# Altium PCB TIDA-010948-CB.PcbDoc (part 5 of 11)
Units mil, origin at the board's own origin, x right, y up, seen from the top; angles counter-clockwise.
Board outline 8100 x 8400 mil, 8 copper layers (L01 - TOP, L02 - GND, L03 - SIG, L04 - GND, L05 - PWR, L06 - SIG, L07 - GND, L08 - BOTTOM), stack 59.656 mil thick; 711 components, 572 nets, 2646 pads, 1325 vias.
Unrouted connection lines stored in the file: 988.
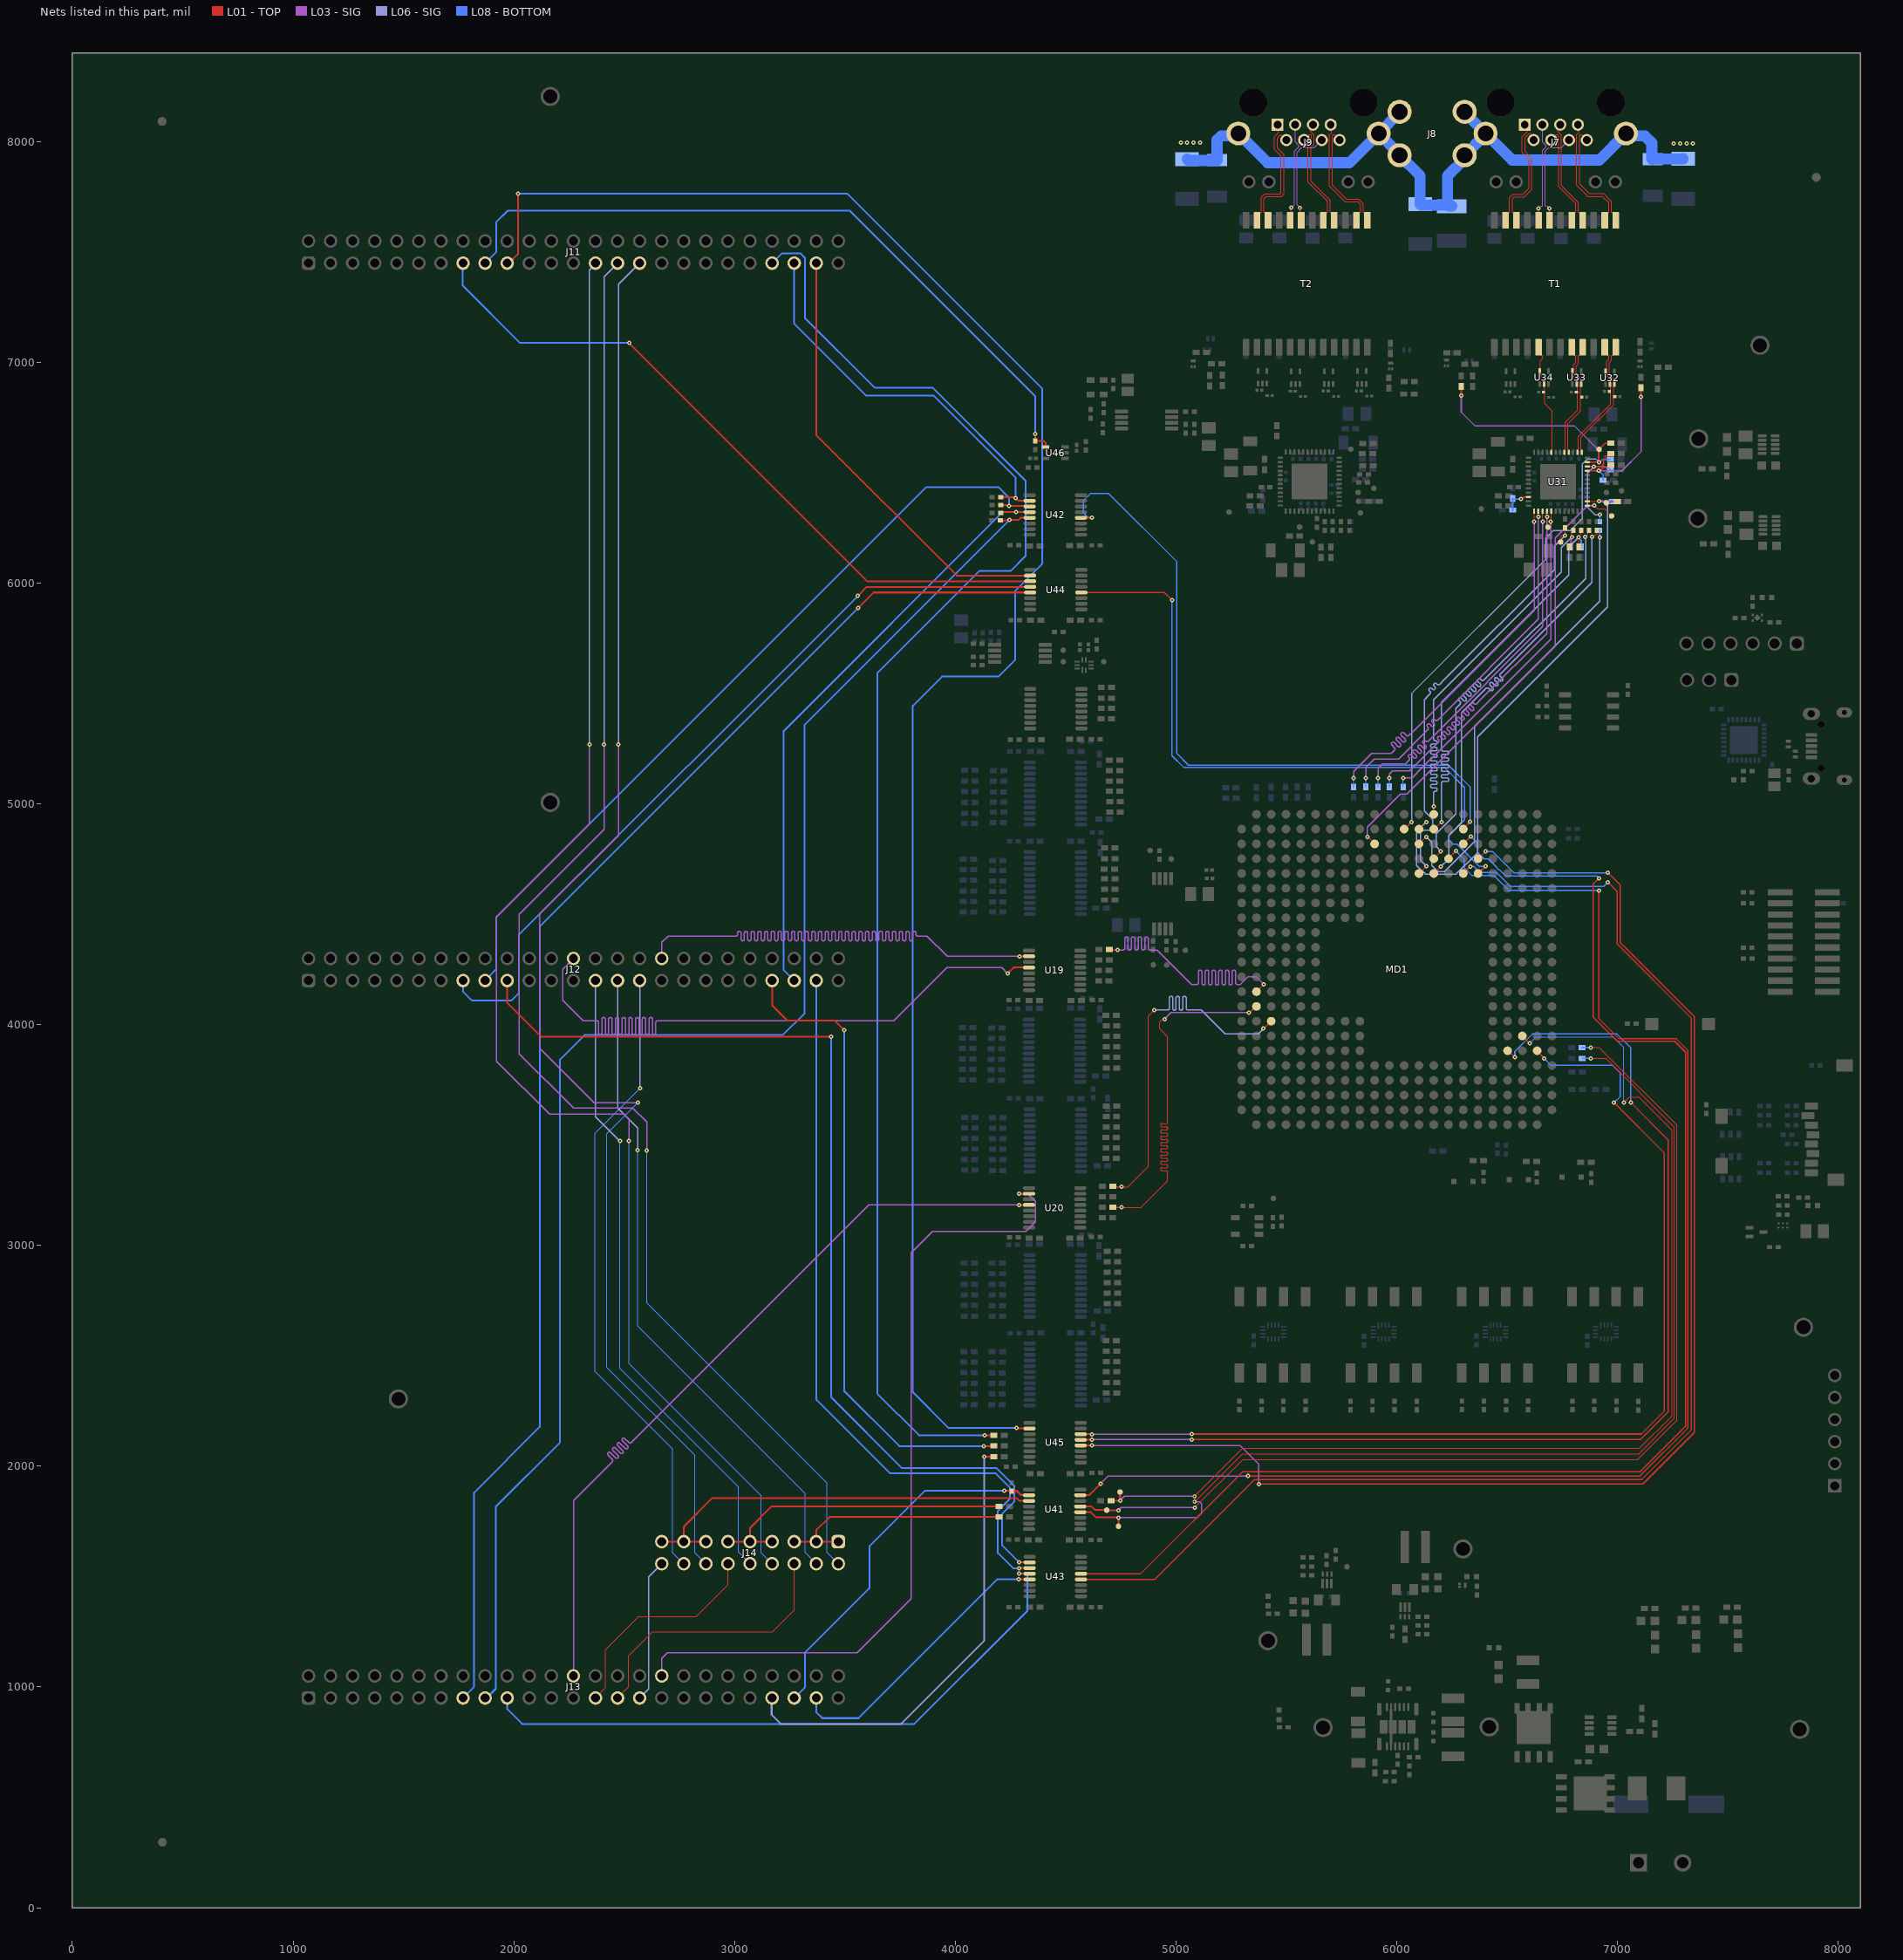
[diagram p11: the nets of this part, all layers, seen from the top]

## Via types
v1: diameter 19.68, hole 7.87, L01 - TOP to L08 - BOTTOM, 1310 vias
v2: diameter 20, hole 7.87, L01 - TOP to L08 - BOTTOM, tented both sides, 7 vias
v3: diameter 200, hole 144, L01 - TOP to L08 - BOTTOM, 6 vias
v4: diameter 20, hole 8, L01 - TOP to L08 - BOTTOM, tented both sides, 2 vias

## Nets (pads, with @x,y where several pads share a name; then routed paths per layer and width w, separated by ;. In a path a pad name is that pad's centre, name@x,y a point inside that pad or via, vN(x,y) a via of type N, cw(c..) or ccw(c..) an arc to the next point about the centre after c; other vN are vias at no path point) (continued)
DOUT_B3_SDM: J12.26 U19.12 | length 3736.3
  L01 - TOP w8: v1(4237,4231.5) 4264.07,4258.57 U19.12@4336.5,4258.57
  L03 - SIG w5.25: J12.26@2270,4299.6 2221.5,4251.1 2221.5,4110.5 2314.5,4017.5 2344.81,4017.5 2376.13,4017.5 cw(c2376.13,4009.88) 2383.75,4009.88 2383.75,3962.17 ccw(c2391.38,3962.17) 2399,3962.17 2399,4024.62 cw(c2406.63,4024.62) 2414.25,4024.62 2414.25,3962.17 ccw(c2421.88,3962.17) 2429.5,3962.17 2429.5,4024.62 cw(c2437.13,4024.62) 2444.75,4024.62 2444.75,3962.17 ccw(c2452.38,3962.17) 2460,3962.17 2460,4024.62 cw(c2467.63,4024.62) 2475.25,4024.62 2475.25,3962.17 ccw(c2482.88,3962.17) 2490.5,3962.17 2490.5,4024.62 cw(c2498.13,4024.62) 2505.75,4024.62 2505.75,3962.17 ccw(c2513.38,3962.17) 2521,3962.17 2521,4024.62 cw(c2528.63,4024.62) 2536.25,4024.62 2536.25,3962.17 ccw(c2543.88,3962.17) 2551.5,3962.17 2551.5,4024.62 cw(c2559.13,4024.62) 2566.75,4024.62 2566.75,3962.17 ccw(c2574.38,3962.17) 2582,3962.17 2582,4024.62 cw(c2589.63,4024.62) 2597.25,4024.62 2597.25,3962.17 ccw(c2604.88,3962.17) 2612.5,3962.17 2612.5,4024.62 cw(c2620.13,4024.62) 2627.75,4024.62 2627.75,3962.17 ccw(c2635.38,3962.17) 2643,3962.17 2643,4009.88 cw(c2650.63,4009.88) 2650.63,4017.5 2653.25,4017.5 3721.5,4017.5 3962.51,4258.51 4209.99,4258.51 v1(4237,4231.5)
DOUT_B4: MD1.N2 R102.1 | length 1990.8
  L01 - TOP w6: R102.1@4695.69,4338 v1(4736,4338) ; MD1.N2@5364.17,4149.21 5364.69,4149.21 5397.48,4182 v1(5398,4182)
  L03 - SIG w5.25: v1(4736,4338) 4757.09,4338 4759.71,4338 ccw(c4759.71,4345.62) 4767.34,4345.62 4767.34,4389.34 cw(c4774.96,4389.34) 4782.59,4389.34 4782.59,4345.11 ccw(c4790.21,4345.11) 4797.84,4345.11 4797.84,4389.34 cw(c4805.46,4389.34) 4813.09,4389.34 4813.09,4345.11 ccw(c4820.71,4345.11) 4828.34,4345.11 4828.34,4389.34 cw(c4835.96,4389.34) 4843.59,4389.34 4843.59,4345.11 ccw(c4851.21,4345.11) 4858.84,4345.11 4858.84,4389.34 cw(c4866.46,4389.34) 4874.09,4389.34 4874.09,4345.62 ccw(c4881.71,4345.62) 4881.71,4338 4908.79,4338 4915,4338 5071,4182 5091.61,4182 5094.24,4182 ccw(c5094.24,4189.62) 5101.86,4189.62 5101.86,4239.34 cw(c5109.49,4239.34) 5117.11,4239.34 5117.11,4187.15 ccw(c5124.74,4187.15) 5132.36,4187.15 5132.36,4239.34 cw(c5139.99,4239.34) 5147.61,4239.34 5147.61,4187.15 ccw(c5155.24,4187.15) 5162.86,4187.15 5162.86,4239.34 cw(c5170.49,4239.34) 5178.11,4239.34 5178.11,4187.15 ccw(c5185.74,4187.15) 5193.36,4187.15 5193.36,4239.34 cw(c5200.99,4239.34) 5208.61,4239.34 5208.61,4187.15 ccw(c5216.24,4187.15) 5223.86,4187.15 5223.86,4239.34 cw(c5231.49,4239.34) 5239.11,4239.34 5239.11,4187.15 ccw(c5246.74,4187.15) 5254.36,4187.15 5254.36,4239.34 cw(c5261.99,4239.34) 5269.61,4239.34 5269.61,4189.62 ccw(c5277.24,4189.62) 5277.24,4182
  L03 - SIG w6: 5277.24,4182 5291.18,4182 5325.15,4215.97 5364.03,4215.97 v1(5398,4182)
DOUT_B4_SDM: J12.34 U19.10 | length 3736.6
  L01 - TOP w8: v1(4291.69,4309.19) 4292,4309.5 U19.10@4336.25,4309.5
  L03 - SIG w5.25: J12.34@2670,4299.6 2670,4372 2699,4401 3003.51,4401 3006.14,4401 ccw(c3006.14,4408.62) 3013.76,4408.62 3013.76,4415.07 cw(c3021.39,4415.07) 3029.01,4415.07 3029.01,4386.9 ccw(c3036.64,4386.9) 3044.26,4386.9 3044.26,4415.07 cw(c3051.89,4415.07) 3059.51,4415.07 3059.51,4386.9 ccw(c3067.14,4386.9) 3074.76,4386.9 3074.76,4415.07 cw(c3082.39,4415.07) 3090.01,4415.07 3090.01,4386.9 ccw(c3097.64,4386.9) 3105.26,4386.9 3105.26,4415.07 cw(c3112.89,4415.07) 3120.51,4415.07 3120.51,4386.9 ccw(c3128.14,4386.9) 3135.76,4386.9 3135.76,4415.07 cw(c3143.39,4415.07) 3151.01,4415.07 3151.01,4386.9 ccw(c3158.64,4386.9) 3166.26,4386.9 3166.26,4415.07 cw(c3173.89,4415.07) 3181.51,4415.07 3181.51,4386.9 ccw(c3189.14,4386.9) 3196.76,4386.9 3196.76,4415.07 cw(c3204.39,4415.07) 3212.01,4415.07 3212.01,4386.9 ccw(c3219.64,4386.9) 3227.26,4386.9 3227.26,4415.07 cw(c3234.89,4415.07) 3242.51,4415.07 3242.51,4386.9 ccw(c3250.14,4386.9) 3257.76,4386.9 3257.76,4415.07 cw(c3265.39,4415.07) 3273.01,4415.07 3273.01,4386.9 ccw(c3280.64,4386.9) 3288.26,4386.9 3288.26,4415.07 cw(c3295.89,4415.07) 3303.51,4415.07 3303.51,4386.9 ccw(c3311.14,4386.9) 3318.76,4386.9 3318.76,4415.07 cw(c3326.39,4415.07) 3334.01,4415.07 3334.01,4386.9 ccw(c3341.64,4386.9) 3349.26,4386.9 3349.26,4415.07 cw(c3356.89,4415.07) 3364.51,4415.07 3364.51,4386.9 ccw(c3372.14,4386.9) 3379.76,4386.9 3379.76,4415.07 cw(c3387.39,4415.07) 3395.01,4415.07 3395.01,4386.9 ccw(c3402.64,4386.9) 3410.26,4386.9 3410.26,4415.07 cw(c3417.89,4415.07) 3425.51,4415.07 3425.51,4386.9 ccw(c3433.14,4386.9) 3440.76,4386.9 3440.76,4415.07 cw(c3448.39,4415.07) 3456.01,4415.07 3456.01,4386.9 ccw(c3463.64,4386.9) 3471.26,4386.9 3471.26,4415.07 cw(c3478.89,4415.07) 3486.51,4415.07 3486.51,4386.9 ccw(c3494.14,4386.9) 3501.76,4386.9 3501.76,4415.07 cw(c3509.39,4415.07) 3517.01,4415.07 3517.01,4386.9 ccw(c3524.64,4386.9) 3532.26,4386.9 3532.26,4415.07 cw(c3539.89,4415.07) 3547.51,4415.07 3547.51,4386.9 ccw(c3555.14,4386.9) 3562.76,4386.9 3562.76,4415.07 cw(c3570.39,4415.07) 3578.01,4415.07 3578.01,4386.9 ccw(c3585.64,4386.9) 3593.26,4386.9 3593.26,4415.07 cw(c3600.89,4415.07) 3608.51,4415.07 3608.51,4386.9 ccw(c3616.14,4386.9) 3623.76,4386.9 3623.76,4415.07 cw(c3631.39,4415.07) 3639.01,4415.07 3639.01,4386.9 ccw(c3646.64,4386.9) 3654.26,4386.9 3654.26,4415.07 cw(c3661.89,4415.07) 3669.51,4415.07 3669.51,4386.9 ccw(c3677.14,4386.9) 3684.76,4386.9 3684.76,4415.07 cw(c3692.39,4415.07) 3700.01,4415.07 3700.01,4386.9 ccw(c3707.64,4386.9) 3715.26,4386.9 3715.26,4415.07 cw(c3722.89,4415.07) 3730.51,4415.07 3730.51,4386.9 ccw(c3738.14,4386.9) 3745.76,4386.9 3745.76,4415.07 cw(c3753.39,4415.07) 3761.01,4415.07 3761.01,4386.9 ccw(c3768.64,4386.9) 3776.26,4386.9 3776.26,4415.07 cw(c3783.89,4415.07) 3791.51,4415.07 3791.51,4386.9 ccw(c3799.14,4386.9) 3806.76,4386.9 3806.76,4415.07 cw(c3814.39,4415.07) 3822.01,4415.07 3822.01,4408.62 ccw(c3829.64,4408.62) 3829.64,4401 3853.01,4401 3871.5,4401 3963.31,4309.19 v1(4291.69,4309.19)
DOUT_B5: MD1.P2 R104.1 | length 1932.2
  L01 - TOP w4.25: v1(4753.71,3172) 4841.5,3172 4962.39,3292.89 4962.39,3328.64 4962.39,3330.76 ccw(c4955.27,3330.76) 4955.27,3337.89 4936.88,3337.89 cw(c4936.88,3345.01) 4936.88,3352.14 4955.61,3352.14 ccw(c4955.61,3359.26) 4955.61,3366.39 4936.88,3366.39 cw(c4936.88,3373.51) 4936.88,3380.64 4955.61,3380.64 ccw(c4955.61,3387.76) 4955.61,3394.89 4936.88,3394.89 cw(c4936.88,3402.01) 4936.88,3409.14 4955.61,3409.14 ccw(c4955.61,3416.26) 4955.61,3423.39 4936.88,3423.39 cw(c4936.88,3430.51) 4936.88,3437.64 4955.61,3437.64 ccw(c4955.61,3444.76) 4955.61,3451.89 4936.88,3451.89 cw(c4936.88,3459.01) 4936.88,3466.14 4955.61,3466.14 ccw(c4955.61,3473.26) 4955.61,3480.39 4936.88,3480.39 cw(c4936.88,3487.51) 4936.88,3494.64 4955.61,3494.64 ccw(c4955.61,3501.76) 4955.61,3508.89 4936.88,3508.89 cw(c4936.88,3516.01) 4936.88,3523.14 4955.61,3523.14 ccw(c4955.61,3530.26) 4955.61,3537.39 4936.88,3537.39 cw(c4936.88,3544.51) 4936.88,3551.64 4955.27,3551.64 ccw(c4955.27,3558.76) 4962.39,3558.76 4962.39,3591.28 4962.39,3943.58 4925.03,3980.94 4925.03,4012.07 4935.76,4022.8 4946.8,4022.8 v1(4948.5,4024.5)
  L01 - TOP w6: R104.1@4712.62,3172 v1(4753.71,3172) ; v1(5330.5,4054.5) 5333.45,4054.5 5361.23,4082.28 MD1.P2@5364.17,4082.28
  L03 - SIG w5.25: v1(4948.5,4024.5) 4948.5,4025 4978,4054.5 v1(5330.5,4054.5)
DOUT_B5_SDM: J13.26 U20.12 | length 3734.9
  L01 - TOP w8: v1(4288.81,3182.99) 4288.86,3183.04 U20.12@4334.11,3183.04
  L03 - SIG w5.25: J13.26@2270,1050 2270,1845 2443.82,2018.82 2445.68,2020.68 ccw(c2440.29,2026.07) 2445.68,2031.46 2427.1,2050.05 cw(c2432.49,2055.44) 2427.1,2060.83 cw(c2432.49,2055.44) 2437.88,2060.83 2461.37,2037.34 ccw(c2466.76,2042.73) 2472.15,2037.34 ccw(c2466.76,2042.73) 2472.15,2048.13 2448.66,2071.62 cw(c2454.06,2077.01) 2448.66,2082.4 cw(c2454.06,2077.01) 2459.45,2082.4 2482.94,2058.91 ccw(c2488.33,2064.3) 2493.72,2058.91 ccw(c2488.33,2064.3) 2493.72,2069.69 2470.23,2093.18 cw(c2475.62,2098.57) 2470.23,2103.97 cw(c2475.62,2098.57) 2481.01,2103.97 2504.5,2080.48 ccw(c2509.89,2085.87) 2515.29,2080.48 ccw(c2509.89,2085.87) 2515.29,2091.26 2491.8,2114.75 cw(c2497.19,2120.14) 2491.8,2125.53 cw(c2497.19,2120.14) 2502.58,2125.53 2521.16,2106.95 ccw(c2526.56,2112.34) 2531.95,2106.95 2547.77,2122.77 3607.99,3182.99 v1(4288.81,3182.99)
DOUT_B6: MD1.R3 R106.1 | length 1858
  L01 - TOP w4.25: v1(4752.71,3265) 4782.5,3265 4875,3357.5 4875,4039 v1(4902,4066)
  L01 - TOP w6: R106.1@4712.4,3265 v1(4752.71,3265) ; v1(5396,3981.92) 5396.84,3981.92 5430.26,4015.35 MD1.R3@5431.1,4015.35
  L06 - SIG w5.25: v1(4902,4066) 4959.29,4066 4961.91,4066 ccw(c4961.91,4073.62) 4969.54,4073.62 4969.54,4120.87 cw(c4977.16,4120.87) 4984.79,4120.87 4984.79,4072.69 ccw(c4992.41,4072.69) 5000.04,4072.69 5000.04,4120.87 cw(c5007.66,4120.87) 5015.29,4120.87 5015.29,4072.69 ccw(c5022.91,4072.69) 5030.54,4072.69 5030.54,4120.87 cw(c5038.16,4120.87) 5045.79,4120.87 5045.79,4073.62 ccw(c5053.41,4073.62) 5053.41,4066 5092.63,4066 5113,4066 5221.5,3957.5 5371.58,3957.5 v1(5396,3981.92)
DOUT_B6_SDM: J13.34 U20.10 | length 3735.9
  L01 - TOP w8: v1(4289.31,3233.67) 4289.61,3233.98 U20.10@4333.86,3233.98
  L03 - SIG w5.25: J13.34@2670,1050 2670,1130 2695.5,1155.5 3556,1155.5 3800,1399.5 3800,1432.74 3800,1508.01 3800,2966.5 3896.5,3063 4320.36,3063 4363.39,3106.02 4363.39,3199.03 4328.74,3233.67 v1(4289.31,3233.67)
DRV_FAULT5: MD1.B16 U42.4 | length 3182.1
  L01 - TOP w6: MD1.B16@6301.18,4885.43 6301.18,4887.3 6332,4918.12 v1(6332,4920)
  L01 - TOP w8: U42.4@4569.14,6295.7 4569.29,6295.85 4618.85,6295.85 v1(4619,6296)
  L08 - BOTTOM w6: v1(4619,6296) 4602.42,6296 4579.38,6319.03 4579.38,6372.49 4612.44,6405.54 4694,6405.54 5003.65,6095.89 5003.65,5227.85 5056.32,5175.18 6233.96,5175.18 6332,5077.14 v1(6332,4920)
DRV_FAULT6: MD1.D15 U41.7 | length 6428.1
  L01 - TOP w6: v1(5326.5,1955.5) 5327.5,1954.5 7100.5,1954.5 7319.14,2173.14 7319.14,3882.36 7266.1,3935.4 7007.1,3935.4 6916,4026.5 v1(6916,4607.66) ; MD1.D15@6234.25,4751.57 6234.25,4752.66 6267.5,4785.91 v1(6267.5,4787)
  L01 - TOP w8: U41.7@4566.14,1868.47 4606.03,1868.47 4657.5,1919.94 v1(4657.5,1920.5)
  L03 - SIG w6: v1(4657.5,1920.5) 4692.5,1955.5 v1(5326.5,1955.5)
  L08 - BOTTOM w6: v1(6267.5,4787) 6304.78,4749.72 6304.78,4711.22 6341.5,4674.5 6441,4674.5 6507.84,4607.66 v1(6916,4607.66)
DRV_FAULT_1: J11.17 R300.2 U46.4 | length 3289.2
  L01 - TOP w8: v1(4362,6674.5) R300.2@4362,6643.69 4399.81,6643.69 4408.71,6634.79 U46.4@4408.71,6615.59
  L08 - BOTTOM w8: J11.17@1870,7449.2 1919.5,7498.7 1919.5,7633.5 1972.6,7686.6 3520.98,7686.6 4362,6845.58 v1(4362,6674.5)
DRV_FAULT_2: J11.45 R299.2 U42.10 | length 1797.9
  L01 - TOP w8: R299.2@4205.69,6389 4266.34,6389 4270.85,6384.49 v1(4274.01,6384.49) 4286.02,6372.48 U42.10@4336.86,6372.48
  L08 - BOTTOM w8: J11.45@3270,7449.2 3270,7174.5 3596,6848.5 3902,6848.5 4274.01,6476.49 v1(4274.01,6384.49)
DRV_FAULT_3: J12.17 R298.2 U42.11 | length 3629.5
  L01 - TOP w8: R298.2@4205.69,6354 4234.77,6354 4240.02,6348.74 v1(4243.19,6348.74) 4335,6348.74 U42.11@4336.86,6346.89
  L08 - BOTTOM w8: J12.17@1870,4199.6 1920,4249.6 1920,4485.5 3869.5,6435 4195,6435 4243.19,6386.81 v1(4243.19,6348.74)
DRV_FAULT_4: J12.45 R297.2 U42.12 | length 2744
  L01 - TOP w8: R297.2@4205.19,6320.5 4206.62,6321.93 v1@4274.35,6321.93 ; v1@4276.39,6321 U42.12@4336.56,6321
  L08 - BOTTOM w8: J12.45@3270,4199.6 3222.5,4247.1 3222.5,5330.06 4213.44,6321 v1(4276,6321)
DRV_FAULT_5: J13.17 R296.2 U42.13 | length 6989
  L01 - TOP w8: R296.2@4204.33,6283.46 4205.85,6284.98 4244.48,6284.98 v1(4246,6286.5) 4246.8,6285.7 4285.2,6285.7 4295.2,6295.7 U42.13@4336.86,6295.7
  L08 - BOTTOM w8: J13.17@1870,950 1876.5,950 1918.5,992 1918.5,1816.5 2209,2107 2209,3841.5 2319.68,3952.18 3218,3952.18 3317.5,4051.68 3317.5,5358 v1(4246,6286.5)
DRV_FAULT_6: J13.45 R292.2 U41.10 | length 1664.3
  L01 - TOP w8: v1(4221,1889) 4222.09,1887.91 4255.41,1887.91 R292.2@4256.5,1886.82
  L01 - TOP w10: R292.2@4256.5,1886.82 4279.69,1886.82 4296.55,1869.95 4332.38,1869.95 U41.10@4333.86,1868.47
  L08 - BOTTOM w8: J13.45@3270,950 3271,950 3318.5,997.5 3318.5,1154.5 3611,1447 3611,1636.5 3863.5,1889 v1(4221,1889)
DRV_OFF5: MD1.C16 U43.5 | length 6566.9
  L01 - TOP w6: U43.5@4569.22,1512.88 4839.88,1512.88 5301,1974 7101,1974 7308.14,2181.14 7308.14,3875.36 7259.1,3924.4 6999.6,3924.4 6890,4034 6890,4636.34 v1(6916.5,4662.84) ; MD1.C16@6301.18,4818.5 6301.84,4818.5 6334.84,4851.5 v1(6335.5,4851.5)
  L08 - BOTTOM w6: v1(6335.5,4851.5) 6366.45,4820.55 6366.45,4779.43 6395.35,4750.53 6415.83,4750.53 6451.36,4715 6451.36,4711.41 6461.81,4700.96 6465.4,4700.96 6493.42,4672.95 6906.14,4672.95 6916.25,4662.84 v1(6916.5,4662.84)
DRV_OFF6: MD1.E16 U43.4 | length 6396.4
  L01 - TOP w6: U43.4@4593.11,1487.41 4904.41,1487.41 5357,1940 7110,1940 7333.54,2163.54 7333.54,4029.96 6998,4365.5 6998,4603.5 v1(6956.5,4645) ; MD1.E16@6301.18,4684.64 6301.41,4684.64 6333.27,4716.5 v1(6333.5,4716.5)
  L01 - TOP w8: U43.4@4569.2,1487.26 4569.35,1487.41 U43.4@4593.11,1487.41
  L08 - BOTTOM w6: v1(6333.5,4716.5) 6349.82,4716.5 6376.82,4689.5 6451.03,4689.5 6515.03,4625.5 6937,4625.5 v1(6956.5,4645)
DRV_OFF_1: J11.19 U45.10 | length 8616.9
  L01 - TOP w8: J11.19@1970,7449.2 1978.2,7449.2 2018.5,7489.5 2018.5,7764 v1(2019,7764.5) ; v1(4277,2172.5) 4278.01,2171.49 4334.85,2171.49 U45.10@4335.86,2170.48
  L08 - BOTTOM w8: v1(2019,7764.5) 3510,7764.5 4394.5,6880 4394.5,6087 4272,5964.5 4272,5653 4195.5,5576.5 3939.8,5576.5 3807.3,5444 3807.3,2335.2 3970,2172.5 v1(4277,2172.5)
DRV_OFF_2: J11.47 U44.10 | length 2010.9
  L01 - TOP w8: J11.47@3370,7449.2 3370,6671 4007.02,6033.98 U44.10@4338.86,6033.98
DRV_OFF_3: J12.19 U43.10 | length 4710.3
  L01 - TOP w8: J12.19@1970,4199.6 1969,4198.6 1969,4101 2125.5,3944.5 v1(3438,3944.5) ; v1(4288.5,1565) 4289.01,1564.49 4336.35,1564.49 U43.10@4336.86,1563.98
  L08 - BOTTOM w8: v1(3438,3944.5) 3438,2311.5 3758.5,1991 4187,1991 4266.9,1911.1 4266.9,1838.5 4211.5,1783.1 4211.5,1642 v1(4288.5,1565)
DRV_OFF_4: J12.47 U43.11 | length 3430.6
  L01 - TOP w8: v1(4288.5,1538) 4288.69,1538.19 4336.67,1538.19 U43.11@4336.86,1538.39
  L08 - BOTTOM w8: J12.47@3370,4199.6 3370,2302.5 3705,1967.5 4182.5,1967.5 4246.66,1903.34 4246.66,1851.16 4193,1797.5 4193,1606.5 4261.5,1538 v1(4288.5,1538)
DRV_OFF_5: J13.19 U43.12 | length 2899.1
  L01 - TOP w8: v1(4288,1512.5) 4288.15,1512.65 4336.71,1512.65 U43.12@4336.86,1512.8
  L08 - BOTTOM w8: J13.19@1970,950 1970,900 2037.5,832.5 3813.5,832.5 4326.62,1345.62 4326.62,1507.96 4321.93,1512.65 4288.15,1512.65 v1(4288,1512.5)
DRV_OFF_6: J13.47 U43.13 | length 1302.4
  L01 - TOP w8: v1(4287.5,1487) 4287.6,1487.1 4336.76,1487.1 U43.13@4336.86,1487.2
  L08 - BOTTOM w8: J13.47@3370,950 3370,886.5 3398,858.5 3561,858.5 4189.5,1487 v1(4287.5,1487)
DRV_SPI_CLK: R65.1 TP37.1 U41.4 | length 4879.1
  L01 - TOP w4.25: v1(5084,1838.5) 5302,2056.5 7096.5,2056.5 7257.5,2217.5 7257.5,3535.5 6946.5,3846.5 v1(6879,3846.5)
  L01 - TOP w8: U41.4@4566.14,1791.7 4614.3,1791.7 4638,1768 ; 4638.5,1767.5 4738.5,1767.5 v1(4739,1767) TP37.1@4739,1727.5
  L03 - SIG w5.25: v1(4739,1767) 5095.5,1767 5115.5,1787 5115.5,1829.5 5106.5,1838.5 v1(5084,1838.5)
  L08 - BOTTOM w6: R65.1@6840.12,3846.5 v1(6879,3846.5)
DRV_SPI_CLK_3V3: J14.1 J14.3 J14.5 R293.2 | length 1105.8
  L01 - TOP w8: J14.5@3270,1658 J14.3@3370,1658 ; J14.1@3470,1658 J14.3@3370,1658 ; R293.2@4198.88,1770 3429.8,1770 3370,1710.2 J14.3@3370,1658
DRV_SPI_CLK_AX12: J11.29 J14.2 | length 6831.3
  L03 - SIG w5.25: v1(2409,5268.5) 2409,4884.5 2024.5,4500 2024.5,3868 2270.12,3622.38 2537.88,3622.38 2602,3558.26 v1(2602,3430.5)
  L06 - SIG w5.25: v1(2409,5268.5) 2409,7388.2 J11.29@2470,7449.2
  L08 - BOTTOM w4.25: v1(2602,3430.5) 2602,2739.5 3419,1922.5 3419,1609 J14.2@3470,1558
DRV_SPI_CLK_AX34: J12.29 J14.4 | length 3014.4
  L06 - SIG w5.25: J12.29@2470,4199.6 2470,3622.12 2560.5,3531.62 v1(2560.5,3431)
  L08 - BOTTOM w4.25: v1(2560.5,3431) 2560.5,2635 3319.5,1876 3319.5,1608.5 J14.4@3370,1558
DRV_SPI_CLK_AX56: J13.29 J14.6 | length 1258
  L01 - TOP w4.25: J13.29@2470,950 2520,1000 2520,1141.5 2628,1249.5 3172,1249.5 3270,1347.5 J14.6@3270,1558
DRV_SPI_CS0_AX12: MD1.U21 U45.6 | length 4744.1
  L01 - TOP w6: v1(5072,2145.5) 7108,2145.5 7211.01,2248.51 7211.01,3419.49 v1(6984,3646.5) ; MD1.U21@6635.83,3881.49 6635.83,3879.83 6668,3847.66 v1(6668,3846)
  L01 - TOP w8: U45.6@4568.33,2144.69 4617.81,2144.69 v1(4618,2144.5)
  L03 - SIG w6: v1(4618,2144.5) 4618.5,2145 5071.5,2145 v1(5072,2145.5)
  L08 - BOTTOM w6: v1(6668,3846) 6699,3815 6978,3815 7012.5,3780.5 7012.5,3675 v1(6984,3646.5)
DRV_SPI_CS1_AX34: MD1.U19 U45.5 | length 5086
  L01 - TOP w6: v1(5071.5,2120.5) 7103.5,2120.5 7228.5,2245.5 7228.5,3478 v1(7060,3646.5) ; MD1.U19@6501.97,3881.49 6504.24,3881.49 6532.73,3853 v1(6535,3853)
  L01 - TOP w8: U45.5@4568.24,2119.4 4617.9,2119.4 v1(4618,2119.5)
  L03 - SIG w6: v1(4618,2119.5) 4618.5,2120 5071,2120 v1(5071.5,2120.5)
  L08 - BOTTOM w6: v1(6535,3853) 6535,3879 6613.5,3957.5 6997.5,3957.5 7060,3895 v1(7060,3646.5)
DRV_SPI_CS2_AX56: MD1.D17 U45.4 | length 6342.2
  L01 - TOP w6: v1(5375,1918) 5376.5,1919.5 7114.5,1919.5 7347.5,2152.5 7347.5,4036.2 7012,4371.7 7012,4632.5 v1(6956.5,4688) ; MD1.D17@6368.11,4751.57 6369.34,4751.57 6402.27,4784.5 v1(6403.5,4784.5)
  L01 - TOP w8: U45.4@4568.29,2093.85 4617.85,2093.85 v1(4618,2094)
  L03 - SIG w6: v1(4618,2094) 5289.5,2094 5375,2008.5 v1(5375,1918)
  L08 - BOTTOM w6: v1(6403.5,4784.5) 6433.5,4784.5 6530.47,4687.53 6956.03,4687.53 v1(6956.5,4688)
DRV_SPI_CS_AX12: J11.43 R303.2 | length 6856.4
  L01 - TOP w8: v1(4132,2140) 4132.5,2139.5 4174.38,2139.5 R303.2@4174.88,2139
  L08 - BOTTOM w8: J11.43@3170,7449.2 3214.74,7493.94 3298.06,7493.94 3319,7473 3319,7200.5 3634.5,6885 3897,6885 4318.5,6463.5 4318.5,6122.87 4250.13,6054.5 4108.5,6054.5 3646.5,5592.5 3646.5,2329 3835.5,2140 v1(4132,2140)
DRV_SPI_CS_AX34: J12.43 R302.2 | length 2901.3
  L01 - TOP w8: J12.43@3170,4199.6 3170,4087.35 3239.85,4017.5 3453.5,4017.5 v1(3496,3975) ; v1(4128.5,2090.5) 4129,2091 4173.88,2091 R302.2@4174.38,2091.5
  L08 - BOTTOM w8: v1(3496,3975) 3496,2341 3746.5,2090.5 v1(4128.5,2090.5)
DRV_SPI_CS_AX56: J13.43 R301.2 | length 2091.2
  L01 - TOP w8: v1(4130.5,2043) 4130.75,2043.25 4174.13,2043.25 R301.2@4174.38,2043.5
  L06 - SIG w8: J13.43@3170,950 3167.83,947.83 3167.83,873.82 3209.15,832.5 3754.5,832.5 4130.5,1208.5 v1(4130.5,2043)
DRV_SPI_D0_3V3: J14.7 J14.9 J14.11 R294.2 | length 1431.8
  L01 - TOP w8: J14.11@2970,1658 J14.9@3070,1658 ; J14.7@3170,1658 J14.9@3070,1658 ; R294.2@4198.88,1818 3167.5,1818 3070,1720.5 J14.9@3070,1658
DRV_SPI_D0_AX12: J11.27 J14.8 | length 6790.4
  L03 - SIG w5.25: v1(2342.5,5268.5) 2342.55,5268.45 2342.55,4908.05 1922,4487.5 1922,3834.5 2162.36,3594.14 2497.98,3594.14 2521,3571.12 v1(2521,3472.5)
  L06 - SIG w5.25: v1(2342.5,5268.5) 2342.5,7416.89 2370,7444.39 J11.27@2370,7449.2
  L08 - BOTTOM w4.25: v1(2521,3472.5) 2521,2465.5 3120,1866.5 3120,1608 J14.8@3170,1558
DRV_SPI_D0_AX34: J12.27 J14.10 | length 2931.5
  L06 - SIG w5.25: J12.27@2370,4199.6 2370,3583.5 v1(2480.5,3473)
  L08 - BOTTOM w4.25: v1(2480.5,3473) 2480.5,2442 3017.5,1905 3017.5,1610.5 J14.10@3070,1558
DRV_SPI_D0_AX56: J13.27 J14.12 | length 1009.1
  L01 - TOP w4.25: J13.27@2370,950 2416,996 2416,1169.5 2565.5,1319 2826,1319 2970,1463 J14.12@2970,1558
DRV_SPI_D1_3V3: J14.13 J14.15 J14.17 U41.11 | length 1891.1
  L01 - TOP w8: J14.17@2670,1658 J14.15@2770,1658 ; J14.13@2870,1658 J14.15@2770,1658 ; U41.11@4333.86,1842.88 4290.62,1842.88 4278.03,1855.47 2898.97,1855.47 2769.81,1726.31 2769.81,1704.5 2770,1704.31 J14.15@2770,1658
DRV_SPI_D1_AX12: J11.31 J14.14 | length 6621.3
  L03 - SIG w5.25: v1(2474,5268.5) 2474,4857.5 2117.5,4501 2117.5,3893 2364.5,3646 v1(2561.5,3646)
  L06 - SIG w5.25: v1(2474,5268.5) 2474,7353.2 J11.31@2570,7449.2
  L08 - BOTTOM w4.25: v1(2561.5,3646) 2422,3506.5 2422,2447.5 2820.5,2049 2820.5,1607.5 J14.14@2870,1558
DRV_SPI_D1_AX34: J12.31 J14.16 | length 2894.3
  L06 - SIG w5.25: J12.31@2570,4199.6 2571,4198.6 2571,3713 v1(2572,3712)
  L08 - BOTTOM w4.25: v1(2572,3712) 2367,3507 2367,2429.5 2720,2076.5 2720,1608 J14.16@2770,1558
DRV_SPI_D1_AX56: J13.31 J14.18 | length 649.4
  L06 - SIG w5.25: J13.31@2570,950 2611,991 2611,1499 J14.18@2670,1558
DRV_SPI_MUX_S56: MD1.E17 U44.4 | length 3048.2
  L01 - TOP w6: U44.4@4594.35,5957.24 4946.94,5957.24 v1(4982.19,5922) ; MD1.E17@6368.11,4684.64 6369.62,4684.64 6401.99,4717 v1(6403.5,4717)
  L01 - TOP w8: U44.4@4571.18,5957.24 U44.4@4594.35,5957.24
  L08 - BOTTOM w6: v1@4981.5,5922 4981.5,5218 5035.32,5164.18 6216.8,5164.18 6307,5073.99 6307,4928 6236.17,4857.17 6236.17,4834.86 6253.89,4817.14 6273.36,4817.14 6373.5,4717 v1(6403.5,4717)
DRV_SPI_MUX_S_12: J11.15 U44.11 | length 3227.7
  L01 - TOP w8: v1(2522.04,7087.46) 3601.11,6008.39 U44.11@4338.86,6008.39
  L08 - BOTTOM w8: J11.15@1770,7449.2 1768.5,7447.7 1768.5,7347 2028.04,7087.46 v1(2522.04,7087.46)
DRV_SPI_MUX_S_34: J12.15 U44.12 | length 3566.9
  L01 - TOP w8: v1(3558.5,5942) 3599.3,5982.8 U44.12@4338.86,5982.8
  L08 - BOTTOM w8: J12.15@1770,4199.6 1770,4149.6 1811.1,4108.5 1989,4108.5 2022.56,4142.06 2022.56,4406.06 v1(3558.5,5942)
DRV_SPI_MUX_S_56: J13.15 U44.13 | length 6486.4
  L01 - TOP w8: v1(3559.5,5886.5) 3630.2,5957.2 U44.13@4338.86,5957.2
  L08 - BOTTOM w8: J13.15@1770,950 1820.5,1000.5 1820.5,1880.5 2117.5,2177.5 2117.5,4444.5 v1(3559.5,5886.5)
DRV_SPI_SDI: MD1.T20 R295.1 TP39.1 | length 5079.9
  L01 - TOP w4.25: v1(5084,1863.18) 5301.31,2080.5 7099.5,2080.5 7247,2228 7247,3521 7096.14,3671.86 7053.36,3671.86 v1(7028,3646.5)
  L01 - TOP w6: MD1.T20@6568.9,3948.42 6568.9,3948.01 6601.5,3915.41 v1(6601.5,3915)
  L01 - TOP w8: R295.1@4705.12,1843.5 4705.37,1843.75 4746.25,1843.75 v1(4746.5,1844) 4746.25,1844.25 TP39.1@4746.25,1882.75 TP39.1@4746,1883
  L03 - SIG w5.25: v1(4746.5,1844) 4765.69,1863.18 v1(5084,1863.18)
  L08 - BOTTOM w4.25: v1(6601.5,3915) 6630.23,3943.73 6980.27,3943.73 7028,3896 v1(7028,3646.5)
DRV_SPI_SDO: R66.1 TP38.1 U41.5 | length 4790.4
  L01 - TOP w4.25: v1(5084.5,1812.5) 5302.5,2030.5 7091.5,2030.5 7268.25,2207.25 7268.25,3544.25 6916,3896.5 v1(6878.5,3896.5)
  L01 - TOP w8: U41.5@4566.14,1817.29 4617.21,1817.29 4633.5,1801 TP38.1@4686,1801 4686.5,1800.5 4738,1800.5 v1(4738.5,1800)
  L03 - SIG w5.25: v1(4738.5,1800) 4738.56,1800 4751.06,1812.5 v1(5084.5,1812.5)
  L08 - BOTTOM w6: R66.1@6839.12,3895.5 6840.12,3896.5 v1(6878.5,3896.5)
E1_TD_A_N: J7.7 T1.14 | length 547.4
  L01 - TOP w3.5: J7.7@6820.39,8076.46 6824.02,8072.83 6824.02,8040.01 6815.24,8031.22 6815.24,7802.58 6866.32,7751.5 6931.5,7751.5 6960.75,7722.25 6960.75,7679.6 6958.7,7677.55 6955.2,7677.55 6942,7664.35 T1.14@6942,7642.5
E1_TD_A_P: J7.8 T1.13 | length 537
  L01 - TOP w3.5: J7.8@6860.55,8006.38 6835.76,8031.17 6832.86,8031.17 6827.74,8026.05 6827.74,7807.76 6871.5,7764 6936.68,7764 6973.25,7727.43 6973.25,7679.6 6975.3,7677.55 6978.8,7677.55 6992,7664.35 T1.13@6992,7642.5
E1_TD_B_N: J7.4 T1.17 | length 469.5
  L01 - TOP w3.5: J7.4@6699.92,8006.38 6724.02,8030.47 6726.92,8030.47 6733.43,8023.96 6733.43,7796.07 6810.75,7718.75 6810.75,7679.6 6808.7,7677.55 6805.2,7677.55 6792,7664.35 T1.17@6792,7642.5
E1_TD_B_P: J7.5 T1.16 | length 486.4
  L01 - TOP w3.5: J7.5@6740.08,8076.46 6730.2,8066.58 6730.2,8044.86 6745.93,8029.14 6745.93,7801.25 6823.25,7723.93 6823.25,7679.6 6825.3,7677.55 6828.8,7677.55 6842,7664.35 T1.16@6842,7642.5
E1_TD_C_N: J7.3 T1.20 | length 459
  L01 - TOP w3.5: T1.20@6642,7642.5 v1(6642,7696.5)
  L03 - SIG w4: v1(6642,7696.5) 6642.4,7696.5 6653.4,7707.5 6658.66,7707.5 6661,7709.84 6661,7960.9 6677.11,7977.01 6677.11,7980.32 6659.76,7997.66 J7.3@6659.76,8076.46
E1_TD_C_P: J7.6 T1.19 | length 464.3
  L01 - TOP w3.5: T1.19@6692,7642.5 v1(6692,7696.5)
  L03 - SIG w4: v1(6692,7696.5) 6691.6,7696.5 6680.6,7707.5 6675.34,7707.5 6673,7709.84 6673,7955.93 6688.89,7971.82 6745.68,7971.82 J7.6@6780.24,8006.38 J7.6@6772.08,8014.54
E1_TD_D_N: J7.1 T1.23 | length 535.3
  L01 - TOP w3.5: T1.23@6492,7642.5 6492,7664.35 6505.2,7677.55 6508.7,7677.55 6510.75,7679.6 6510.75,7744.68 6526.57,7760.5 6572.5,7760.5 6599.5,7787.5 6599.5,7918 6568,7949.5 6568,8022.11 6591.59,8045.7 6591.59,8064.32 J7.1@6579.45,8076.46
E1_TD_D_P: J7.2 T1.22 | length 529
  L01 - TOP w3.5: T1.22@6542,7642.5 6542,7664.35 6528.8,7677.55 6525.3,7677.55 6523.25,7679.6 6523.25,7739.5 6531.75,7748 6577.68,7748 6612,7782.32 6612,7923.18 6580.5,7954.68 6580.5,8016.93 6600.31,8036.74 6603.21,8036.74 6619.61,8020.35 J7.2@6619.61,8006.38
E2_TD_A_N: J9.7 T2.14 | length 539.8
  L01 - TOP w3.5: J9.7@5700.39,8076.46 5704.02,8072.83 5704.02,8040.01 5695.24,8031.22 5695.24,7797.76 5766.5,7726.5 5822.25,7726.5 5835.75,7713 5835.75,7679.6 5833.7,7677.55 5830.2,7677.55 5817,7664.35 T2.14@5817,7642.5
E2_TD_A_P: J9.8 T2.13 | length 529.4
  L01 - TOP w3.5: J9.8@5740.55,8006.38 5715.76,8031.17 5712.86,8031.17 5707.74,8026.05 5707.74,7802.94 5771.68,7739 5827.43,7739 5848.25,7718.18 5848.25,7679.6 5850.3,7677.55 5853.8,7677.55 5867,7664.35 T2.13@5867,7642.5
E2_TD_B_N: J9.4 T2.17 | length 479.2
  L01 - TOP w3.5: J9.4@5579.92,8006.38 5604.02,8030.47 5606.92,8030.47 5612.73,8024.66 5612.73,7992.79 5598.5,7978.56 5598.5,7815.5 5685.75,7728.25 5685.75,7679.6 5683.7,7677.55 5680.2,7677.55 5667,7664.35 T2.17@5667,7642.5
E2_TD_B_P: J9.5 T2.16 | length 496.1
  L01 - TOP w3.5: J9.5@5620.08,8076.46 5610.2,8066.58 5610.2,8044.86 5625.23,8029.84 5625.23,7987.61 5611,7973.38 5611,7820.68 5698.25,7733.43 5698.25,7679.6 5700.3,7677.55 5703.8,7677.55 5717,7664.35 T2.16@5717,7642.5
E2_TD_C_N: J9.3 T2.20 | length 464.1
  L01 - TOP w3.5: T2.20@5517,7642.5 5521,7646.5 v1(5521,7700)
  L03 - SIG w4: v1(5521,7700) 5522.75,7700 5536.25,7713.5 5536.25,7956.15 5557.11,7977.01 5557.11,7980.32 5539.76,7997.66 J9.3@5539.76,8076.46 J9.3@5536,8072.69
E2_TD_C_P: J9.6 T2.19 | length 451.3
  L01 - TOP w3.5: v1(5562,7699.5) 5562,7647.5 T2.19@5567,7642.5
  L03 - SIG w4: v1(5562,7699.5) 5562,7699.75 5548.25,7713.5 5548.25,7951.18 5568.89,7971.82 5625.68,7971.82 J9.6@5660.24,8006.38
E2_TD_D_N: J9.1 T2.23 | length 542.6
  L01 - TOP w3.5: T2.23@5367,7642.5 5367,7664.35 5380.2,7677.55 5383.7,7677.55 5385.75,7679.6 5385.75,7746.18 5402.07,7762.5 5471,7762.5 5476,7767.5 5476,7935 5446,7965 5446,8021.68 5463.16,8038.84 5463.16,8072.74 J9.1@5459.45,8076.46
E2_TD_D_P: J9.2 T2.22 | length 530.5
  L01 - TOP w3.5: T2.22@5417,7642.5 5417,7664.35 5403.8,7677.55 5400.3,7677.55 5398.25,7679.6 5398.25,7741 5407.25,7750 5476.18,7750 5488.5,7762.32 5488.5,7940.18 5458.5,7970.18 5458.5,8016.5 5472,8030 5475.98,8030 J9.2@5499.61,8006.38
EARTH_GND: C141.2 C150.1 C183.2 J7.13 J7.14 J8.1 J8.2 J8.3 J8.4 J9.13 J9.14 R249.1 R252.2 R288.1 | length 3384.2
  L08 - BOTTOM w50: R288.1@5050,7920.55 5056.42,7914.13 5184.45,7914.13 C183.2@5186,7915.68 5186,8007.01 5204.14,8025.15 5270.94,8025.15 J9.14@5282.09,8036.3 5414.39,7904 5785.61,7904 J9.13@5917.91,8036.3 ; J8.2@6012.56,8134.43 cw(c6004.16,8134.43) 6010.1,8128.48 J9.13@5917.91,8036.3 ; C150.1@6249,7707.24 6236,7707.24 C150.1@6231.34,7711.9 ; J8.4@6307.44,8134.43 ccw(c6315.84,8134.43) 6309.9,8128.49 J7.14@6402.09,8036.3 ; R249.1@7297,7921.55 7296.06,7920.61 7159.94,7920.61 C141.2@7159,7919.68 7157.56,7919.68 7155,7922.24 7155,7994 7123.85,8025.15 7049.06,8025.15 J7.13@7037.91,8036.3 6917.61,7916 6522.39,7916 J7.14@6402.09,8036.3 ; J9.13@5917.91,8036.3 6009.68,7944.54 cw(c6002.71,7937.57) J8.1@6012.56,7937.57 6106,7844.13 R252.2@6106,7716.55 6110.66,7711.9 C150.1@6231.34,7711.9 ; C150.1@6231.34,7711.9 6229.5,7713.74 6229.5,7843.6 6307.44,7921.54 J8.3@6307.44,7937.57 6399.2,8029.34 ccw(c6392.24,8036.3) J7.14@6402.09,8036.3
  other v1: 7254,7991 7283,7991 7313,7991 7341,7991 5021,7994 5050,7994 5080,7994 5108,7994
ETH1_GPIO_1: R219.1 R227.2 U31.22 | length 127.6
  L01 - TOP w6: v1(6561.86,6380.53) 6565.56,6380.53 6575.14,6390.1 U31.22@6596.14,6390.1
  L08 - BOTTOM w6: R219.1@6526,6382.88 6528.35,6380.53 v1(6561.86,6380.53)
  L08 - BOTTOM w8: R227.2@6525.62,6330.5 6526,6330.88 R219.1@6526,6382.88
ETH1_LED_0: MD1.B12 R216.1 R224.2 R251.1 TP31.1 U31.47 | length 3224.3
  L01 - TOP w6: MD1.B12@6033.46,4885.43 6034.45,4885.43 6066.02,4917 v1(6067,4917) ; U31.47@6863.86,6547.58 v1@6915.83,6547.56 ; v1@6914.36,6549.03 v1@6915.83,6547.56 ; R224.2@6969.38,6633.5 6944.5,6633.5 TP31.1@6916.5,6605.5 6916.18,6605.18 6916.18,6547.85 v1(6915.86,6547.53)
  L01 - TOP w8: v1(6292,6849) 6292.25,6849.25 6292.25,6889.63 R251.1@6292.5,6889.88
  L03 - SIG w6: v1(6292,6849) 6292,6773.97 6353.49,6712.49 6803.5,6712.5 6915.86,6600.14 v1(6915.86,6547.53)
  L06 - SIG w6: v1(6067,4917) 6067,5499.5 6673.87,6106.37 6673.87,6202.98 6708.54,6237.65 6786.39,6237.65 6840.22,6291.48 6840.22,6538.71 6864.06,6562.54 6900.84,6562.54 v1(6915.86,6547.53)
  L08 - BOTTOM w6: v1(6915.86,6547.53) 6919.02,6547.53 6932.04,6560.55 R216.1@6967.39,6560.55
ETH1_LED_1: R217.1 R225.2 R228.1 U31.46 | length 525.1
  L01 - TOP w5: v1(6893.36,6527.53) 6894.17,6528.34 6926.67,6528.34 6936.86,6538.53 6936.86,6555.53 6943.36,6562.03 6943.36,6574.03 ; 6945.55,6576.22 R225.2@6960.43,6576.22
  L01 - TOP w6: U31.46@6863.86,6527.9 U31.46@6864.04,6527.71 ; U31.46@6864.23,6527.53 v1(6893.36,6527.53) v1@6894.36,6528.53 ; 6943.36,6574.03 6945.55,6576.22 ; R225.2@6960.43,6576.22 R225.2@6969.24,6585.03
  L06 - SIG w6: v1(6893.36,6527.53) 6863.92,6498.09 6863.92,6343.08 6898,6309 v1(6920.5,6309)
  L08 - BOTTOM w4.25: R228.1@6920.5,6278.69 v1(6920.5,6309)
  L08 - BOTTOM w6: v1(6893.36,6527.53) 6941.14,6527.53 6947.33,6521.34 6959.69,6521.34 R217.1@6967.5,6513.53
ETH1_LED_2: R218.1 R226.2 R250.1 U31.45 | length 687.5
  L01 - TOP w5: v1(6914.86,6508.69) 6918.83,6508.69 6928.65,6518.5 6933.5,6518.5 6941.27,6526.27 6960.76,6526.27 R226.2@6970.07,6535.58
  L01 - TOP w6: U31.45@6863.86,6508.21 6864.27,6508.62 6914.79,6508.62 v1(6914.86,6508.69) v1@6915.57,6509.39
  L01 - TOP w8: R250.1@7105.5,6884.38 7105.75,6884.13 7105.75,6844.25 v1(7106,6844)
  L03 - SIG w6: v1(6914.86,6508.69) 7020.19,6508.69 7106,6594.5 v1(7106,6844)
  L08 - BOTTOM w6: v1(6914.86,6508.69) 6915.2,6508.69 6934.71,6489.18 R218.1@6934.71,6464.94
ETH1_RGMII1_RD0: MD1.A14 R213.1 R221.2 R233.1 | length 1998.1
  L01 - TOP w4.25: v1(6167,4989) 6167.16,4988.84 6167.16,4952.52 MD1.A14@6167.32,4952.36 ; R221.2@6782,6163.12 6782,6181.2 6792.86,6192.05 v1(6792.86,6208.03) 6792.86,6232.94 R233.1@6798.98,6239.06
  L06 - SIG w5.25: v1(6167,4989) 6167,5031.7 6167,5049.57 cw(c6174.62,5049.57) 6174.62,5057.2 6175.51,5057.2 ccw(c6175.51,5064.82) 6175.51,5072.45 6160.32,5072.45 cw(c6160.32,5080.07) 6160.32,5087.7 6175.51,5087.7 ccw(c6175.51,5095.32) 6175.51,5102.95 6160.32,5102.95 cw(c6160.32,5110.57) 6160.32,5118.2 6175.51,5118.2 ccw(c6175.51,5125.82) 6175.51,5133.45 6160.32,5133.45 cw(c6160.32,5141.07) 6160.32,5148.7 6175.51,5148.7 ccw(c6175.51,5156.32) 6175.51,5163.95 6160.32,5163.95 cw(c6160.32,5171.57) 6160.32,5179.2 6175.51,5179.2 ccw(c6175.51,5186.82) 6175.51,5194.45 6160.32,5194.45 cw(c6160.32,5202.07) 6160.32,5209.7 6175.51,5209.7 ccw(c6175.51,5217.32) 6175.51,5224.95 6160.32,5224.95 cw(c6160.32,5232.57) 6160.32,5240.2 6175.51,5240.2 ccw(c6175.51,5247.82) 6175.51,5255.45 6160.32,5255.45 cw(c6160.32,5263.07) 6160.32,5270.7 6175.51,5270.7 ccw(c6175.51,5278.32) 6175.51,5285.95 6174.62,5285.95 cw(c6174.62,5293.57) 6167,5293.57 6167,5321.52 6167,5471.5 6745,6049.5 6745,6160.17 v1(6792.86,6208.03)
  L08 - BOTTOM w8: R213.1@6786.66,6164.23 6790.62,6168.19 6790.62,6205.79 v1(6792.86,6208.03)
ETH1_RGMII1_RD1: MD1.B14 R214.1 R222.2 R234.1 | length 1999.1
  L01 - TOP w4.25: MD1.B14@6167.32,4885.43 6168.62,4885.43 6201.2,4918 v1(6202.5,4918) ; R222.2@6825,6163.12 6823.86,6164.26 v1(6823.86,6208.03) 6823.86,6208.68 6835,6219.82 R234.1@6835,6238.81
  L06 - SIG w5.25: v1(6202.5,4918) 6202.5,5076.13 6202.5,5094.01 cw(c6210.12,5094.01) 6210.12,5101.64 6228.14,5101.64 ccw(c6228.14,5109.26) 6228.14,5116.89 6209.28,5116.89 cw(c6209.28,5124.51) 6209.28,5132.14 6228.14,5132.14 ccw(c6228.14,5139.76) 6228.14,5147.39 6209.28,5147.39 cw(c6209.28,5155.01) 6209.28,5162.64 6228.14,5162.64 ccw(c6228.14,5170.26) 6228.14,5177.89 6209.28,5177.89 cw(c6209.28,5185.51) 6209.28,5193.14 6228.14,5193.14 ccw(c6228.14,5200.76) 6228.14,5208.39 6209.28,5208.39 cw(c6209.28,5216.01) 6209.28,5223.64 6228.14,5223.64 ccw(c6228.14,5231.26) 6228.14,5238.89 6210.12,5238.89 cw(c6210.12,5246.51) 6202.5,5246.51 6202.5,5279.76 6202.5,5459.5 6779,6036 6779,6163.17 v1(6823.86,6208.03)
  L08 - BOTTOM w8: v1(6823.86,6208.03) 6823.86,6204.87 6834.79,6193.94 R214.1@6834.79,6164.18
ETH1_RGMII1_RD2: MD1.D14 R237.1 | length 2008.7
  L01 - TOP w4.25: MD1.D14@6167.32,4751.57 6167.32,4751.7 6200,4784.37 v1(6200,4784.5) ; v1(6853.86,6208.53) 6865.33,6220 6865.33,6233.64 R237.1@6871,6239.31
  L06 - SIG w5.25: v1(6200,4784.5) 6177.92,4806.58 6177.92,4863.92 6267.72,4953.72 6267.72,5432.62 6284.78,5449.68 6286.64,5451.54 ccw(c6281.25,5456.93) 6286.64,5462.32 6282.1,5466.86 cw(c6287.49,5472.25) 6282.1,5477.65 cw(c6287.49,5472.25) 6292.88,5477.65 6302.59,5467.94 ccw(c6307.98,5473.33) 6313.38,5467.94 ccw(c6307.98,5473.33) 6313.38,5478.72 6303.67,5488.43 cw(c6309.06,5493.82) 6303.67,5499.21 cw(c6309.06,5493.82) 6314.45,5499.21 6324.16,5489.5 ccw(c6329.55,5494.89) 6334.94,5489.5 ccw(c6329.55,5494.89) 6334.94,5500.29 6325.23,5510 cw(c6330.63,5515.39) 6325.23,5520.78 cw(c6330.63,5515.39) 6336.02,5520.78 6345.73,5511.07 ccw(c6351.12,5516.46) 6356.51,5511.07 ccw(c6351.12,5516.46) 6356.51,5521.85 6346.8,5531.56 cw(c6352.19,5536.95) 6346.8,5542.35 cw(c6352.19,5536.95) 6357.58,5542.35 6367.29,5532.64 ccw(c6372.69,5538.03) 6378.08,5532.64 ccw(c6372.69,5538.03) 6378.08,5543.42 6368.37,5553.13 cw(c6373.76,5558.52) 6368.37,5563.91 cw(c6373.76,5558.52) 6379.15,5563.91 6383.69,5559.37 ccw(c6389.08,5564.76) 6394.47,5559.37 6410.06,5574.96 6855.6,6020.5 6855.6,6206.79 v1(6853.86,6208.53)
ETH1_RGMII1_RD3: MD1.E14 R238.1 | length 2009
  L01 - TOP w4.25: MD1.E14@6167.32,4684.64 6167.98,4684.64 6198.34,4715 v1(6199,4715) ; v1(6883.86,6208.53) 6888.03,6208.53 6897.03,6217.52 6900.68,6217.52 6906.72,6223.57 R238.1@6906.72,6239.31
  L06 - SIG w5.25: v1(6199,4715) 6234.94,4750.94 6234.94,4855.94 6293,4914 6293,5412 6391.52,5510.52 6404.15,5523.15 cw(c6409.55,5517.76) 6414.94,5523.15 6423.8,5514.3 ccw(c6429.19,5519.69) 6434.58,5514.3 ccw(c6429.19,5519.69) 6434.58,5525.08 6423.02,5536.64 cw(c6428.41,5542.03) 6423.02,5547.42 cw(c6428.41,5542.03) 6433.8,5547.42 6445.36,5535.86 ccw(c6450.76,5541.25) 6456.15,5535.86 ccw(c6450.76,5541.25) 6456.15,5546.65 6444.59,5558.21 cw(c6449.98,5563.6) 6444.59,5568.99 cw(c6449.98,5563.6) 6455.37,5568.99 6466.93,5557.43 ccw(c6472.32,5562.82) 6477.71,5557.43 ccw(c6472.32,5562.82) 6477.71,5568.21 6468.86,5577.07 cw(c6474.25,5582.46) 6468.86,5587.86 6479.28,5598.28 6883.86,6002.86 v1(6883.86,6208.53)
ETH1_RGMII1_RX_CTL: MD1.B13 R215.1 R223.2 TP33.1 U31.38 | length 2658.1
  L01 - TOP w4.25: MD1.B13@6100.39,4885.43 6100.66,4885.43 6133.23,4918 v1(6133.5,4918) ; U31.38@6863.86,6370.42 6863.91,6370.47 6915.8,6370.47 v1(6915.86,6370.53) ; v1@6916.11,6370.28 v1(6915.86,6370.53) ; R215.1@6998.88,6368.5 6996.91,6370.47 6973.29,6370.47 6968.32,6365.5 6951.62,6365.5 TP33.1@6949.44,6363.32 6943.83,6363.32 6936.62,6370.53 v1(6915.86,6370.53)
  L06 - SIG w5.25: v1(6133.5,4918) 6089.5,4874 6089.5,4721.5 6130.25,4680.75 6267.47,4680.75 6365.5,4778.78 6365.5,5303 6955.25,5892.75 6955.25,6347.61 6933.58,6369.28 6917.1,6369.28 v1(6915.86,6370.53)
  L08 - BOTTOM w4.25: R223.2@6973.23,6370.53 R223.2@6974.49,6369.26
  L08 - BOTTOM w8: v1(6915.86,6370.53) R223.2@6973.23,6370.53
ETH1_RGMII1_RX_ER: MD1.C13 R228.2 | length 2094.5
  L01 - TOP w4.25: MD1.C13@6100.39,4818.5 6101.2,4818.5 6132.7,4850 v1(6133.5,4850)
  L06 - SIG w5.25: v1(6133.5,4850) 6158.33,4825.17 6158.33,4720.67 6186.88,4692.12 6216.37,4692.12 6352.97,4828.71 6352.97,5350.95 6920,5917.98 v1(6920,6207.5)
  L08 - BOTTOM w4.25: v1(6920,6207.5) 6920,6238.81 R228.2@6920.5,6239.31
ETH1_RGMII1_RXC: MD1.E13 R230.1 TP12.1 | length 2009.8
  L01 - TOP w4.25: MD1.E13@6100.39,4684.64 6100.77,4684.64 6133.13,4717 v1(6133.5,4717) ; TP12.1@6742.36,6185.53 6742.36,6209.86 6748.03,6215.53 v1(6762.36,6215.53) 6762.36,6250.67 R230.1@6762.5,6250.81
  L06 - SIG w5.25: v1(6133.5,4717) 6133.5,4717.63 6107.38,4743.75 6107.38,4869.08 6119.65,4881.35 6148.85,4881.35 6162,4894.5 6162,4929.5 6124.48,4967.02 6124.48,5471.98 6148.81,5496.31 6150.66,5498.16 ccw(c6145.27,5503.56) 6150.66,5508.95 6147.73,5511.88 cw(c6153.12,5517.27) 6147.73,5522.67 cw(c6153.12,5517.27) 6158.51,5522.67 6161.8,5519.38 ccw(c6167.19,5524.77) 6172.58,5519.38 ccw(c6167.19,5524.77) 6172.58,5530.16 6169.29,5533.45 cw(c6174.69,5538.84) 6169.29,5544.23 cw(c6174.69,5538.84) 6180.08,5544.23 6183.01,5541.3 ccw(c6188.41,5546.69) 6193.8,5541.3 6211.98,5559.48 6713,6060.5 6713,6166.17 v1(6762.36,6215.53)
ETH1_RGMII1_TD0: R113.1 U31.28 | length 1911.9
  L01 - TOP w4.25: U31.28@6680.79,6325.14 U31.28@6680.79,6325.14 6680.82,6299.06 v1(6680.86,6299.03)
  L03 - SIG w5.25: v1(5967,5117) 5967,5135 5981.25,5149.25 6057.75,5149.25 6186.83,5278.33 6188.69,5280.19 ccw(c6183.3,5285.58) 6188.69,5290.97 6186.93,5292.73 cw(c6192.32,5298.12) 6186.93,5303.51 cw(c6192.32,5298.12) 6197.71,5303.51 6206.73,5294.5 ccw(c6212.12,5299.89) 6217.52,5294.5 ccw(c6212.12,5299.89) 6217.52,5305.28 6208.5,5314.3 cw(c6213.89,5319.69) 6208.5,5325.08 cw(c6213.89,5319.69) 6219.28,5325.08 6228.3,5316.06 ccw(c6233.69,5321.45) 6239.08,5316.06 ccw(c6233.69,5321.45) 6239.08,5326.85 6230.06,5335.86 cw(c6235.46,5341.26) 6230.06,5346.65 cw(c6235.46,5341.26) 6240.85,5346.65 6249.87,5337.63 ccw(c6255.26,5343.02) 6260.65,5337.63 ccw(c6255.26,5343.02) 6260.65,5348.41 6251.63,5357.43 cw(c6257.02,5362.82) 6251.63,5368.21 cw(c6257.02,5362.82) 6262.41,5368.21 6271.43,5359.2 ccw(c6276.82,5364.59) 6282.22,5359.2 ccw(c6276.82,5364.59) 6282.22,5369.98 6273.2,5379 cw(c6278.59,5384.39) 6273.2,5389.78 cw(c6278.59,5384.39) 6283.98,5389.78 6293,5380.76 ccw(c6298.39,5386.16) 6303.78,5380.76 ccw(c6298.39,5386.16) 6303.78,5391.55 6294.77,5400.56 cw(c6300.16,5405.96) 6294.77,5411.35 cw(c6300.16,5405.96) 6305.55,5411.35 6314.57,5402.33 ccw(c6319.96,5407.72) 6325.35,5402.33 ccw(c6319.96,5407.72) 6325.35,5413.11 6316.33,5422.13 cw(c6321.72,5427.52) 6316.33,5432.92 cw(c6321.72,5427.52) 6327.12,5432.92 6336.13,5423.9 ccw(c6341.52,5429.29) 6346.92,5423.9 ccw(c6341.52,5429.29) 6346.92,5434.68 6337.9,5443.7 cw(c6343.29,5449.09) 6337.9,5454.48 cw(c6343.29,5449.09) 6348.68,5454.48 6350.44,5452.72 ccw(c6355.83,5458.12) 6361.22,5452.72 6382.8,5474.3 6680.39,5771.89 6680.39,6298.56 v1(6680.86,6299.03)
  L08 - BOTTOM w4.25: R113.1@5967,5076.62 v1(5967,5117)
ETH1_RGMII1_TD1: R114.1 U31.27 | length 1792.2
  L01 - TOP w4.25: v1(6660.86,6277.53) 6660.98,6277.65 6660.98,6325.02 U31.27@6661.1,6325.14
  L03 - SIG w5.25: v1(5915,5116.5) 5915,5160.45 5936.05,5181.5 6040,5181.5 6054.35,5195.85 6056.21,5197.71 ccw(c6050.81,5203.1) 6056.21,5208.49 6054.63,5210.07 cw(c6060.02,5215.46) 6054.63,5220.85 cw(c6060.02,5215.46) 6065.41,5220.85 6077.09,5209.17 ccw(c6082.49,5214.56) 6087.88,5209.17 ccw(c6082.49,5214.56) 6087.88,5219.95 6076.19,5231.63 cw(c6081.59,5237.03) 6076.19,5242.42 cw(c6081.59,5237.03) 6086.98,5242.42 6098.66,5230.73 ccw(c6104.05,5236.13) 6109.44,5230.73 ccw(c6104.05,5236.13) 6109.44,5241.52 6097.76,5253.2 cw(c6103.15,5258.59) 6097.76,5263.98 cw(c6103.15,5258.59) 6108.54,5263.98 6120.23,5252.3 ccw(c6125.62,5257.69) 6131.01,5252.3 ccw(c6125.62,5257.69) 6131.01,5263.08 6119.33,5274.77 cw(c6124.72,5280.16) 6119.33,5285.55 cw(c6124.72,5280.16) 6130.11,5285.55 6131.69,5283.97 ccw(c6137.08,5289.36) 6142.47,5283.97 6156.12,5297.62 6660.86,5802.36 v1(6660.86,6277.53)
  L08 - BOTTOM w4.25: R114.1@5915,5076.12 v1(5915,5116.5)
ETH1_RGMII1_TD2: R115.1 U31.26 | length 1699.6
  L01 - TOP w4.25: v1@6641.39,6299.56 U31.26@6641.42,6325.14
  L03 - SIG w5.25: v1(5860,5117) 5860,5166 5897.5,5203.5 6008.5,5203.5 6139.35,5334.35 6141.21,5336.21 ccw(c6135.82,5341.6) 6141.21,5346.99 6139.07,5349.14 cw(c6144.46,5354.53) 6139.07,5359.92 cw(c6144.46,5354.53) 6149.85,5359.92 6157.45,5352.32 ccw(c6162.84,5357.72) 6168.23,5352.32 ccw(c6162.84,5357.72) 6168.23,5363.11 6160.63,5370.7 cw(c6166.02,5376.09) 6160.63,5381.49 cw(c6166.02,5376.09) 6171.42,5381.49 6173.56,5379.34 ccw(c6178.95,5384.73) 6184.34,5379.34 6199.41,5394.41 6641.36,5836.36 v1(6641.36,6299.53)
  L08 - BOTTOM w4.25: R115.1@5860,5076.62 v1(5860,5117)
ETH1_RGMII1_TD3: R116.1 U31.25 | length 1824.3
  L01 - TOP w4.25: U31.25@6621.73,6325.14 6622.3,6324.58 6622.3,6278.09 v1(6622.86,6277.53)
  L03 - SIG w5.25: v1(5804.5,5117) 5804.5,5147 5886,5228.5 5974.36,5228.5 5987.9,5242.04 5989.76,5243.9 ccw(c5984.37,5249.29) 5989.76,5254.68 5977.45,5267 cw(c5982.84,5272.39) 5977.45,5277.78 cw(c5982.84,5272.39) 5988.23,5277.78 6005.39,5260.62 ccw(c6010.78,5266.01) 6016.17,5260.62 ccw(c6010.78,5266.01) 6016.17,5271.41 5999.01,5288.56 cw(c6004.4,5293.95) 5999.01,5299.35 cw(c6004.4,5293.95) 6009.8,5299.35 6026.95,5282.19 ccw(c6032.34,5287.58) 6037.74,5282.19 ccw(c6032.34,5287.58) 6037.74,5292.97 6020.58,5310.13 cw(c6025.97,5315.52) 6020.58,5320.91 cw(c6025.97,5315.52) 6031.36,5320.91 6043.68,5308.6 ccw(c6049.07,5313.99) 6054.46,5308.6 6078.89,5333.03 6622.86,5877 v1(6622.86,6277.53)
  L08 - BOTTOM w4.25: R116.1@5804.5,5076.12 v1(5804.5,5117)
ETH1_RGMII1_TX_CTL: MD1.C10 TP11.1 U31.37 | length 2137.6
  L01 - TOP w4.25: v1(5866.5,4850) 5867.3,4850 5898.8,4818.5 MD1.C10@5899.61,4818.5 ; U31.37@6863.86,6350.73 6863.96,6350.63 v1(6895.26,6350.63) 6909.35,6336.54 6928.87,6336.54 6940.41,6336.54 TP11.1@6973.29,6303.66
  L03 - SIG w5.25: v1(5866.5,4850) 5866.5,4893.91 6017.22,5044.63 6046.64,5044.63 6717.02,5715 6717.02,6203.97 6863.67,6350.63 v1(6895.26,6350.63)
ETH1_RGMII1_TXC: R117.1 TP10.1 U31.29 | length 1580.5
  L01 - TOP w4.25: TP10.1@6684.86,6253.03 6696.81,6264.98 6696.81,6276.48 v1(6697.86,6277.53) 6699.17,6278.83 6699.17,6323.83 U31.29@6700.47,6325.14
  L03 - SIG w5.25: v1(6029,5117.5) 6069,5117.5 6115.68,5164.18 6183.48,5231.98 6697.86,5746.36 v1(6697.86,6277.53)
  L08 - BOTTOM w4.25: R117.1@6029,5076.12 v1(6029,5117.5)
ETH1_TD_A_N: C143.2 T1.11 U31.2 U32.2 U32.5 | length 585.3
  L01 - TOP w3.5: T1.11@6942,7067.5 6942,7045.65 6955.2,7032.45 6958.7,7032.45 6960.75,7030.4 6960.75,7015 6950,7004.25 U32.5@6950,6959.08 ; U32.5@6945.81,6959.13 6945.87,6959.08 U32.5@6950,6959.08 ; C143.2@6963.02,6868 C143.2@6969,6868 ; U32.2@6965.5,6900.87 6968.94,6900.87 6969,6900.92 6969,6919.31 6950,6938.31 U32.5@6950,6959.08 ; U32.2@6969,6900.87 C143.2@6969,6868 ; U31.2@6821.41,6595.69 U31.2@6818.58,6592.86 U31.2@6821.41,6595.69 ; U31.2@6821.41,6595.69 U31.2@6821.41,6604.21 ; U31.2@6821.41,6595.69 U31.2@6821.41,6604.21 ; U31.2@6821.41,6604.21 6822.18,6604.97 6822.18,6664.68 6969,6811.5 C143.2@6969,6868
ETH1_TD_A_P: C142.2 T1.12 U31.1 U32.3 | length 581.2
  L01 - TOP w3.5: U32.3@6981.5,6900.87 C142.2@6981.5,6844 ; U32.3@6985.19,6900.87 6981.56,6900.87 6981.5,6900.92 6981.5,6924.48 6962.5,6943.48 6962.5,6999.07 6973.25,7009.82 6973.25,7030.4 6975.3,7032.45 6978.8,7032.45 6992,7045.65 T1.12@6992,7067.5 ; C142.2@6987.48,6844 C142.2@6981.5,6844 ; U31.1@6835.44,6595.69 U31.1@6838.27,6592.86 U31.1@6835.44,6595.69 ; U31.1@6835.44,6595.69 U31.1@6835.44,6604.21 ; U31.1@6835.44,6595.69 U31.1@6835.44,6604.21 ; U31.1@6835.44,6604.21 6834.68,6604.97 6834.68,6659.5 6981.5,6806.32 C142.2@6981.5,6844
ETH1_TD_B_N: C145.2 T1.8 U31.5 U33.2 U33.5 | length 549.6
  L01 - TOP w3.5: T1.8@6792,7067.5 6792,7045.65 6805.2,7032.45 6808.7,7032.45 6810.75,7030.4 6810.75,6998.83 6800,6988.08 U33.5@6800,6959.58 ; U33.5@6795.81,6959.63 6795.87,6959.58 U33.5@6800,6959.58 ; C145.2@6813.52,6865.5 C145.2@6819.32,6865.5 ; U33.2@6815.5,6901.37 6819.26,6901.37 6819.32,6901.42 6819.32,6922.14 6815.4,6926.06 6812.76,6926.06 6800,6938.82 U33.5@6800,6959.58 ; U33.2@6819.32,6901.37 C145.2@6819.32,6865.5 ; U31.5@6762.36,6595.69 U31.5@6759.53,6592.86 U31.5@6762.36,6595.69 ; U31.5@6762.36,6595.69 U31.5@6762.36,6604.21 ; U31.5@6762.36,6595.69 U31.5@6762.36,6604.21 ; U31.5@6762.36,6604.21 6763.12,6604.97 6763.12,6727.09 6819.32,6783.3 C145.2@6819.32,6865.5
ETH1_TD_B_P: C144.2 T1.9 U31.4 U33.3 | length 545.2
  L01 - TOP w3.5: U33.3@6831.82,6901.37 C144.2@6831.82,6842 ; U33.3@6835.19,6901.37 6831.88,6901.37 6831.82,6901.42 6831.82,6927.32 6820.58,6938.56 6817.94,6938.56 6812.5,6944 6812.5,6982.9 6823.25,6993.65 6823.25,7030.4 6825.3,7032.45 6828.8,7032.45 6842,7045.65 T1.9@6842,7067.5 ; C144.2@6837.98,6842 C144.2@6831.82,6842 ; U31.4@6776.38,6595.69 U31.4@6779.21,6592.86 U31.4@6776.38,6595.69 ; U31.4@6776.38,6595.69 U31.4@6776.38,6604.21 ; U31.4@6776.38,6595.69 U31.4@6776.38,6604.21 ; U31.4@6776.38,6604.21 6775.62,6604.97 6775.62,6721.92 6831.82,6778.12 C144.2@6831.82,6842
ETH1_TD_C_N: C147.2 T1.5 U31.8 U34.2 U34.5 | length 538
  L01 - TOP w3.5: T1.5@6642,7067.5 6642,7045.65 6655.2,7032.45 6658.7,7032.45 6660.75,7030.4 6660.75,7017.5 6650,7006.75 U34.5@6650,6959.63 ; U34.5@6646.81,6959.63 6649.94,6959.63 6650,6959.58 6650,6941.82 6670,6921.82 U34.2@6670,6901.42 ; C147.2@6664.02,6865 C147.2@6670,6865 ; U34.2@6666.5,6901.37 6666.56,6901.42 U34.2@6670,6901.42 ; C147.2@6670,6865 6670,6878.82 U34.2@6670,6901.42 ; C147.2@6670,6865 6670,6812.82 6704.06,6778.76 6704.06,6604.97 U31.8@6703.3,6604.21 ; U31.8@6703.3,6595.69 U31.8@6703.3,6604.21 ; U31.8@6703.3,6595.69 U31.8@6700.47,6592.86 U31.8@6703.3,6595.69 ; U31.8@6703.3,6595.69 U31.8@6703.3,6604.21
